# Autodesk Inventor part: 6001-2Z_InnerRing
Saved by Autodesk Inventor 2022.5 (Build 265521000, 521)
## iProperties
Created: 2024-12
Part Number: 6001-2Z_InnerRing
Material: Generic
Document SubType Name: Modeling
Designer: AdminForWorker
Density: 1 g/cm^3
Appearance: Default
Title: 6001-2Z_InnerRing
Author: AdminForWorker
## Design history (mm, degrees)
feature "Body1"
body "Solid1"
